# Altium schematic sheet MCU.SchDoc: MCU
size A3; DocumentNumber: MB1167; Revision: B.1; SheetNumber: 2; SheetTotal: 17; Project: STM327x6G-EVAL
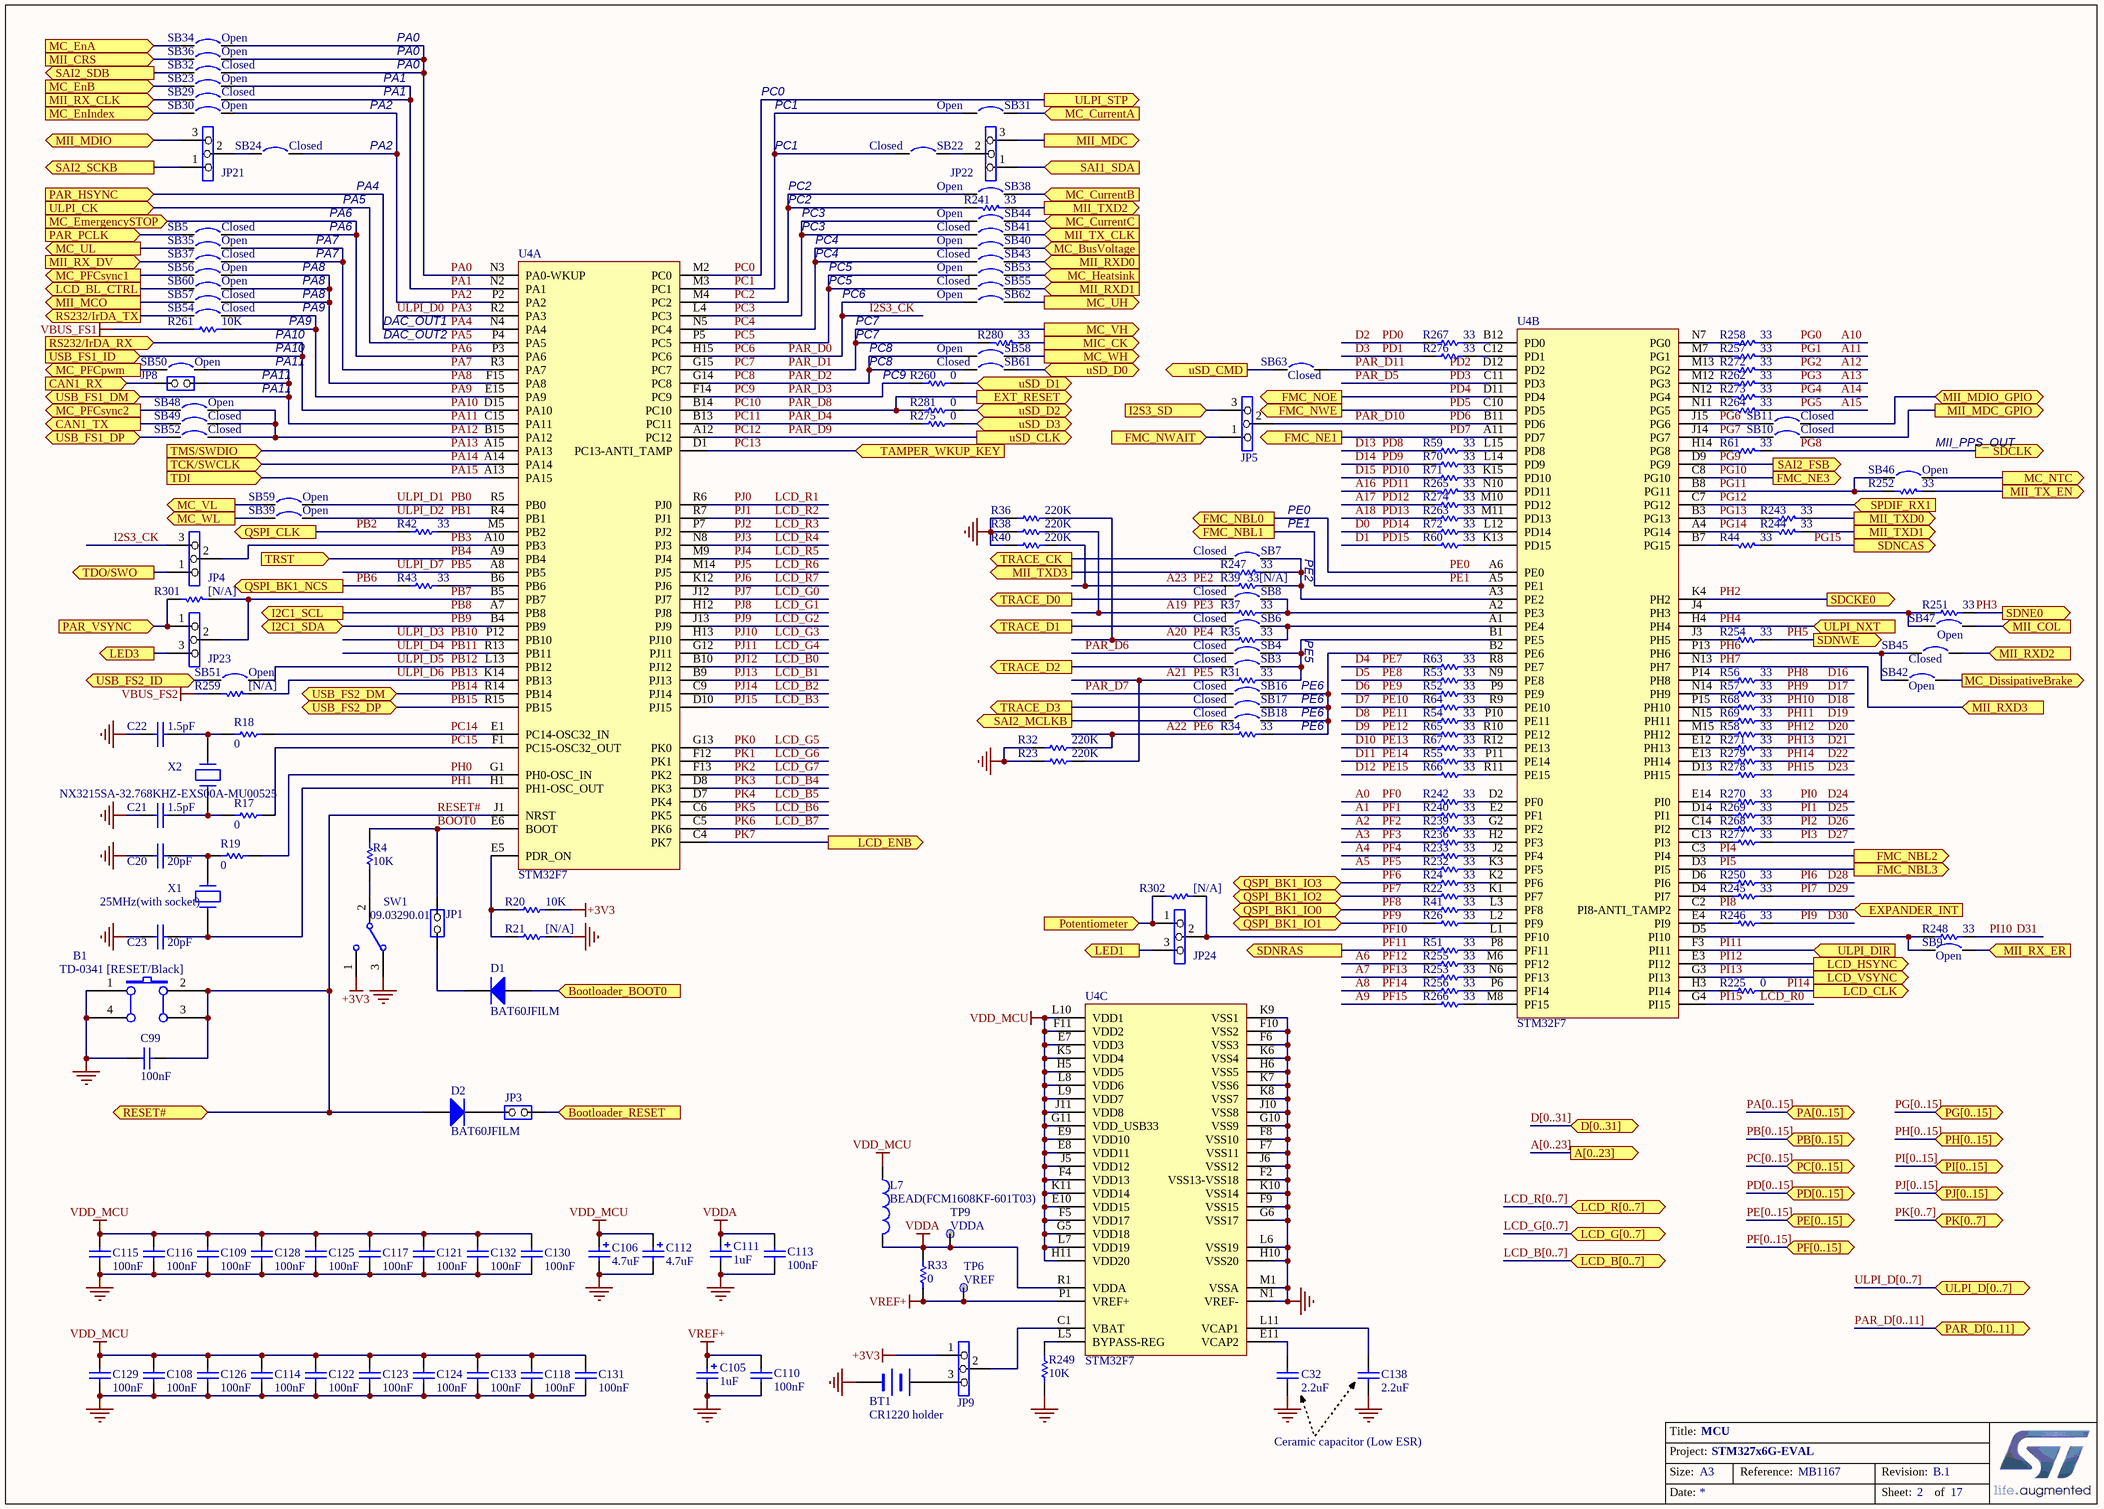
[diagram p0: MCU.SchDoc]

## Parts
B1  TD-0341 [RESET/Black]  [PB10]
BT1  CR1220 holder  [BAT_2SM_CR1220]
C20  20pF  [0603C]
C21  1.5pF  [0603C]
C22  1.5pF  [0603C]
C23  20pF  [0603C]
C32  2.2uF  [1206C]
C99  100nF  [0603C]
C105  1uF  [TAN-A]
C106  4.7uF  [TAN-A]
C108  100nF  [0402C]
C109  100nF  [0402C]
C110  100nF  [0402C]
C111  1uF  [TAN-A]
C112  4.7uF  [TAN-A]
C113  100nF  [0402C]
C114  100nF  [0402C]
C115  100nF  [0402C]
C116  100nF  [0402C]
C117  100nF  [0402C]
C118  100nF  [0402C]
C121  100nF  [0402C]
C122  100nF  [0402C]
C123  100nF  [0402C]
C124  100nF  [0402C]
C125  100nF  [0402C]
C126  100nF  [0402C]
C128  100nF  [0402C]
C129  100nF  [0402C]
C130  100nF  [0402C]
C131  100nF  [0402C]
C132  100nF  [0402C]
C133  100nF  [0402C]
C138  2.2uF  [1206C]
D1  BAT60JFILM  [SOD-323]
D2  BAT60JFILM  [SOD-323]
JP1  (no value)  [SIP2]
JP3  (no value)  [SIP2]
JP4  (no value)  [SIP3]
JP5  (no value)  [SIP3]
JP8  (no value)  [SIP2]
JP9  (no value)  [SIP3]
JP21  (no value)  [SIP3]
JP22  (no value)  [SIP3]
JP23  (no value)  [SIP3]
JP24  (no value)  [SIP3]
L7  BEAD(FCM1608KF-601T03)  [0603L]
R4  10K  [0603R]
R17  0  [0603R]
R18  0  [0603R]
R19  0  [0603R]
R20  10K  [0603R]
R21  [N/A]  [0603R]
R22  33  [0402R]
R23  220K  [0603R]
R24  33  [0402R]
R26  33  [0402R]
R31  33  [0402R]
R32  220K  [0603R]
R33  0  [0603R]
R34  33  [0402R]
R35  33  [0402R]
R36  220K  [0603R]
R37  33  [0402R]
R38  220K  [0603R]
R39  33[N/A]  [0402R]
R40  220K  [0603R]
R41  33  [0402R]
R42  33  [0402R]
R43  33  [0402R]
R44  33  [0402R]
R51  33  [0402R]
R52  33  [0402R]
R53  33  [0402R]
R54  33  [0402R]
R55  33  [0402R]
R56  33  [0402R]
R57  33  [0402R]
R58  33  [0402R]
R59  33  [0402R]
R60  33  [0402R]
R61  33  [0402R]
R63  33  [0402R]
R64  33  [0402R]
R65  33  [0402R]
R66  33  [0402R]
R67  33  [0402R]
R68  33  [0402R]
R69  33  [0402R]
R70  33  [0402R]
R71  33  [0402R]
R72  33  [0402R]
R225  0  [0603R]
R232  33  [0402R]
R233  33  [0402R]
R236  33  [0402R]
R239  33  [0402R]
R240  33  [0402R]
R241  33  [0603R]
R242  33  [0402R]
R243  33  [0603R]
R244  33  [0603R]
R245  33  [0402R]
R246  33  [0402R]
R247  33  [0603R]
R248  33  [0402R]
R249  10K  [0603R]
R250  33  [0402R]
R251  33  [0402R]
R252  33  [0603R]
R253  33  [0402R]
R254  33  [0402R]
R255  33  [0402R]
R256  33  [0402R]
R257  33  [0402R]
R258  33  [0402R]
R259  [N/A]  [0603R]
R260  0  [0603R]
R261  10K  [0603R]
R262  33  [0402R]
R263  33  [0402R]
R264  33  [0402R]
R265  33  [0402R]
R266  33  [0402R]
R267  33  [0402R]
R268  33  [0402R]
R269  33  [0402R]
R270  33  [0402R]
R271  33  [0402R]
R272  33  [0402R]
R273  33  [0402R]
R274  33  [0402R]
R275  0  [0603R]
R276  33  [0402R]
R277  33  [0402R]
R278  33  [0402R]
R279  33  [0402R]
R280  33  [0603R]
R281  0  [0603R]
R301  [N/A]  [0603R]
R302  [N/A]  [0603R]
SB3  Closed  [SB_0603]
SB4  Closed  [SB_0603]
SB5  Closed  [SB_0603]
SB6  Closed  [SB_0603]
SB7  Closed  [SB_0603]
SB8  Closed  [SB_0603]
SB9  Open  [SB_0603]
SB10  Closed  [SB_0603]
SB11  Closed  [SB_0603]
SB16  Closed  [SB_0603]
SB17  Closed  [SB_0603]
SB18  Closed  [SB_0603]
SB22  Closed  [SB_0603]
SB23  Open  [SB_0603]
SB24  Closed  [SB_0603]
SB29  Closed  [SB_0603]
SB30  Open  [SB_0603]
SB31  Open  [SB_0603]
SB32  Closed  [SB_0603]
SB34  Open  [SB_0603]
SB35  Open  [SB_0603]
SB36  Open  [SB_0603]
SB37  Closed  [SB_0603]
SB38  Open  [SB_0603]
SB39  Open  [SB_0603]
SB40  Open  [SB_0603]
SB41  Closed  [SB_0603]
SB42  Open  [SB_0603]
SB43  Closed  [SB_0603]
SB44  Open  [SB_0603]
SB45  Closed  [SB_0603]
SB46  Open  [SB_0603]
SB47  Open  [SB_0603]
SB48  Open  [SB_0603]
SB49  Closed  [SB_0603]
SB50  Open  [SB_0603]
SB51  Open  [SB_0603]
SB52  Closed  [SB_0603]
SB53  Open  [SB_0603]
SB54  Closed  [SB_0603]
SB55  Closed  [SB_0603]
SB56  Open  [SB_0603]
SB57  Closed  [SB_0603]
SB58  Open  [SB_0603]
SB59  Open  [SB_0603]
SB60  Open  [SB_0603]
SB61  Closed  [SB_0603]
SB62  Open  [SB_0603]
SB63  Closed  [SB_0603]
SW1  09.03290.01  [SW1_3TH_2R54_10X2R5]
TP6  VREF  [TP]
TP9  VDDA  [TP]
U4  STM32F7  [BGA216_0R8_13X13_SKT]  (parts A,B,C of 3)
X1  25MHz(with socket)  [XTAL_socket]
X2  NX3215SA-32.768KHZ-EXS00A-MU00525  [XTAL_2SM_3R2X1R5]

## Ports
A[0..23] (out), Bootloader_BOOT0 (in), Bootloader_RESET (in), CAN1_RX (in), CAN1_TX (out), D[0..31] (bidir), EXPANDER_INT (in), EXT_RESET (out), FMC_NBL0 (out), FMC_NBL1 (out), FMC_NBL2 (out), FMC_NBL3 (out), FMC_NE1 (out), FMC_NE3 (out), FMC_NOE (out), FMC_NWAIT (in), FMC_NWE (out), I2C1_SCL (out), I2C1_SDA (bidir), I2S3_SD (in), LCD_B[0..7] (bidir), LCD_BL_CTRL (out), LCD_CLK (out), LCD_ENB (out), LCD_G[0..7] (bidir), LCD_HSYNC (out), LCD_R[0..7] (bidir), LCD_VSYNC (out), LED1 (out), LED3 (out), MC_BusVoltage (in), MC_CurrentA (in), MC_CurrentB (in), MC_CurrentC (in), MC_DissipativeBrake (out), MC_EmergencySTOP (in), MC_EnA (in), MC_EnB (in), MC_EnIndex (in), MC_Heatsink (in), MC_NTC (out), MC_PFCpwm (out), MC_PFCsync1 (out), MC_PFCsync2 (out), MC_UH (out), MC_UL (out), MC_VH (out), MC_VL (out), MC_WH (out), MC_WL (out), MIC_CK (out), MII_COL (in), MII_CRS (in), MII_MCO (out), MII_MDC (out), MII_MDC_GPIO (out), MII_MDIO (bidir), MII_MDIO_GPIO (bidir), MII_RX_CLK (in), MII_RX_DV (in), MII_RX_ER (in), MII_RXD0 (in), MII_RXD1 (in), MII_RXD2 (in), MII_RXD3 (in), MII_TX_CLK (in), MII_TX_EN (out), MII_TXD0 (out), MII_TXD1 (out), MII_TXD2 (out), MII_TXD3 (out), PA[0..15] (bidir), PAR_D[0..11] (bidir), PAR_HSYNC (in), PAR_PCLK (in), PAR_VSYNC (in), PB[0..15] (bidir), PC[0..15] (bidir), PD[0..15] (bidir), PE[0..15] (bidir), PF[0..15] (bidir), PG[0..15] (bidir), PH[0..15] (bidir), PI[0..15] (bidir), PJ[0..15] (bidir), PK[0..7] (bidir), Potentiometer (in), QSPI_BK1_IO0 (bidir), QSPI_BK1_IO1 (bidir), QSPI_BK1_IO2 (bidir), QSPI_BK1_IO3 (bidir), QSPI_BK1_NCS (out), QSPI_CLK (out), RESET# (bidir), RS232/IrDA_RX (in), RS232/IrDA_TX (out), SAI1_SDA (in), SAI2_FSB (out), SAI2_MCLKB (out), SAI2_SCKB (out), SAI2_SDB (out), SDCKE0 (out), SDCLK (out), SDNCAS (out), SDNE0 (out), SDNRAS (out), SDNWE (out), SPDIF_RX1 (in), TAMPER_WKUP_KEY (in), TCK/SWCLK (in), TDI (in), TDO/SWO (out), TMS/SWDIO (in), TRACE_CK (out), TRACE_D0 (out), TRACE_D1 (out), TRACE_D2 (out), TRACE_D3 (out), TRST (in), ULPI_CK (in), ULPI_D[0..7] (bidir), ULPI_DIR (in), ULPI_NXT (in), ULPI_STP (out), USB_FS1_DM (bidir), USB_FS1_DP (bidir), USB_FS1_ID (in), USB_FS2_DM (bidir), USB_FS2_DP (bidir), USB_FS2_ID (bidir), uSD_CLK (out), uSD_CMD (out), uSD_D0 (bidir), uSD_D1 (bidir), uSD_D2 (bidir), uSD_D3 (bidir)

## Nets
+3V3: JP9.1 R20.2 SW1.1
GND: B1.1(A0) B1.4(A1) BT1.2(-) C20.2 C21.2 C22.2 C23.2 C32.2 C99.1 C105.2 C106.2 C108.2 C109.2 C110.1 C111.2 C112.2 C113.1 C114.2 C115.2 C116.2 C117.2 C118.2 C121.2 C122.2 C123.2 C124.2 C125.2 C126.2 C128.2 C129.2 C130.2 C131.2 C132.2 C133.2 C138.2 R21.2 R23.1 R32.1 R36.1 R38.1 R40.1 R249.1 SW1.3 U4.F2(VSS13-VSS18) U4.F6(VSS3) U4.F7(VSS11) U4.F8(VSS10) U4.F9(VSS15) U4.F10(VSS2) U4.G6(VSS17) U4.G10(VSS9) U4.H6(VSS5) U4.H10(VSS20) U4.J6(VSS12) U4.J10(VSS8) U4.K6(VSS4) U4.K7(VSS6) U4.K8(VSS7) U4.K9(VSS1) U4.K10(VSS14) U4.L6(VSS19) U4.M1(VSSA) U4.N1(VREF-)
VBUS_FS1: R261.2
VBUS_FS2: R259.1
VDD_MCU: C106.1 C108.1 C109.1 C112.1 C114.1 C115.1 C116.1 C117.1 C118.1 C121.1 C122.1 C123.1 C124.1 C125.1 C126.1 C128.1 C129.1 C130.1 C131.1 C132.1 C133.1 L7.1 U4.E7(VDD3) U4.E8(VDD11) U4.E9(VDD10) U4.E10(VDD15) U4.F4(VDD13) U4.F5(VDD17) U4.F11(VDD2) U4.G5(VDD18) U4.G11(VDD_USB33) U4.H5(VDD5) U4.H11(VDD20) U4.J5(VDD12) U4.J11(VDD8) U4.K5(VDD4) U4.K11(VDD14) U4.L7(VDD19) U4.L8(VDD6) U4.L9(VDD7) U4.L10(VDD1)
VDDA: C111.1 C113.2 L7.2 R33.1 TP9.1 U4.R1(VDDA)
VREF+: C105.1 C110.2 R33.2 TP6.1 U4.P1(VREF+)
A0: R242.2  [also labelled PF0]
A1: R240.2  [also labelled PF1]
A2: R239.2  [also labelled PF2]
A3: R236.2  [also labelled PF3]
A4: R233.2  [also labelled PF4]
A5: R232.2  [also labelled PF5]
A6: R255.2  [also labelled PF12]
A7: R253.2  [also labelled PF13]
A8: R256.2  [also labelled PF14]
A9: R266.2  [also labelled PF15]
A10: R258.2  [also labelled PG0]
A11: R257.2  [also labelled PG1]
A12: R272.2  [also labelled PG2]
A13: R262.2  [also labelled PG3]
A14: R273.2  [also labelled PG4]
A15: R264.2  [also labelled PG5]
A16: R265.1  [also labelled PD11]
A17: R274.2  [also labelled PD12]
A18: R263.2  [also labelled PD13]
A19: R37.2 R38.2  [also labelled PE3]
A20: R35.2 R36.2  [also labelled PE4]
A21: R23.2 R31.2  [also labelled PE5]
A22: R32.2 R34.2  [also labelled PE6]
A23: R39.2 R40.2  [also labelled PE2]
BOOT0: JP1.2(NO) R4.1 U4.E6(BOOT)
Bootloader_BOOT0: D1.1(A) ; port Bootloader_BOOT0
Bootloader_RESET: JP3.2(NO) ; port Bootloader_RESET
CAN1_RX: JP8.2(NO) ; port CAN1_RX
CAN1_TX: SB49.1 ; port CAN1_TX
D0: R72.2  [also labelled PD14]
D1: R60.2  [also labelled PD15]
D2: R267.2  [also labelled PD0]
D3: R276.2  [also labelled PD1]
D4: R63.2  [also labelled PE7]
D5: R53.2  [also labelled PE8]
D6: R52.2  [also labelled PE9]
D7: R64.2  [also labelled PE10]
D8: R54.2  [also labelled PE11]
D9: R65.2  [also labelled PE12]
D10: R67.2  [also labelled PE13]
D11: R55.2  [also labelled PE14]
D12: R66.2  [also labelled PE15]
D13: R59.2  [also labelled PD8]
D14: R70.2  [also labelled PD9]
D15: R71.2  [also labelled PD10]
D16: R56.1  [also labelled PH8]
D17: R57.1  [also labelled PH9]
D18: R68.1  [also labelled PH10]
D19: R69.1  [also labelled PH11]
D20: R58.1  [also labelled PH12]
D21: R271.1  [also labelled PH13]
D22: R279.1  [also labelled PH14]
D23: R278.1  [also labelled PH15]
D24: R270.1  [also labelled PI0]
D25: R269.1  [also labelled PI1]
D26: R268.1  [also labelled PI2]
D27: R277.1  [also labelled PI3]
D28: R250.1  [also labelled PI6]
D29: R245.1  [also labelled PI7]
D30: R246.1  [also labelled PI9]
D31: R248.1  [also labelled PI10]
FMC_NWAIT: JP5.1 ; port FMC_NWAIT
I2S3_CK: JP4.3 SB62.1 U4.H15(PC6)  [also labelled PAR_D0, PC6]
I2S3_SD: JP5.3 ; port I2S3_SD
LCD_B0: U4.B10(PJ12)  [also labelled PJ12]
LCD_B1: U4.B9(PJ13)  [also labelled PJ13]
LCD_B2: U4.C9(PJ14)  [also labelled PJ14]
LCD_B3: U4.D10(PJ15)  [also labelled PJ15]
LCD_B4: U4.D8(PK3)  [also labelled PK3]
LCD_B5: U4.D7(PK4)  [also labelled PK4]
LCD_B6: U4.C6(PK5)  [also labelled PK5]
LCD_B7: U4.C5(PK6)  [also labelled PK6]
LCD_BL_CTRL: SB60.1 ; port LCD_BL_CTRL
LCD_G0: U4.J12(PJ7)  [also labelled PJ7]
LCD_G1: U4.H12(PJ8)  [also labelled PJ8]
LCD_G2: U4.J13(PJ9)  [also labelled PJ9]
LCD_G3: U4.H13(PJ10)  [also labelled PJ10]
LCD_G4: U4.G12(PJ11)  [also labelled PJ11]
LCD_G5: U4.G13(PK0)  [also labelled PK0]
LCD_G6: U4.F12(PK1)  [also labelled PK1]
LCD_G7: U4.F13(PK2)  [also labelled PK2]
LCD_R0: U4.G4(PI15)  [also labelled PI15]
LCD_R1: U4.R6(PJ0)  [also labelled PJ0]
LCD_R2: U4.R7(PJ1)  [also labelled PJ1]
LCD_R3: U4.P7(PJ2)  [also labelled PJ2]
LCD_R4: U4.N8(PJ3)  [also labelled PJ3]
LCD_R5: U4.M9(PJ4)  [also labelled PJ4]
LCD_R6: U4.M14(PJ5)  [also labelled PJ5]
LCD_R7: U4.K12(PJ6)  [also labelled PJ6]
LED1: JP24.3 ; port LED1
LED3: JP23.3 ; port LED3
MC_BusVoltage: SB40.2 ; port MC_BusVoltage
MC_CurrentA: SB31.2 ; port MC_CurrentA
MC_CurrentB: SB38.2 ; port MC_CurrentB
MC_CurrentC: SB44.2 ; port MC_CurrentC
MC_DissipativeBrake: SB42.2 ; port MC_DissipativeBrake
MC_EnA: SB34.1 ; port MC_EnA
MC_EnB: SB23.1 ; port MC_EnB
MC_EnIndex: SB30.1 ; port MC_EnIndex
MC_Heatsink: SB53.2 ; port MC_Heatsink
MC_NTC: SB46.2 ; port MC_NTC
MC_PFCpwm: SB50.1 ; port MC_PFCpwm
MC_PFCsync1: SB56.1 ; port MC_PFCsync1
MC_PFCsync2: SB48.1 ; port MC_PFCsync2
MC_UH: SB62.2 ; port MC_UH
MC_UL: SB35.1 ; port MC_UL
MC_VL: SB59.1 ; port MC_VL
MC_WH: SB58.2 ; port MC_WH
MC_WL: SB39.1 ; port MC_WL
MIC_CK: R280.2 ; port MIC_CK
MII_COL: SB47.2 ; port MII_COL
MII_CRS: SB36.1 ; port MII_CRS
MII_MCO: SB57.1 ; port MII_MCO
MII_MDC: JP22.3 ; port MII_MDC
MII_MDC_GPIO: SB10.2 ; port MII_MDC_GPIO
MII_MDIO: JP21.3 ; port MII_MDIO
MII_MDIO_GPIO: SB11.2 ; port MII_MDIO_GPIO
MII_RX_CLK: SB29.1 ; port MII_RX_CLK
MII_RX_DV: SB37.1 ; port MII_RX_DV
MII_RX_ER: SB9.2 ; port MII_RX_ER
MII_RXD0: SB43.2 ; port MII_RXD0
MII_RXD1: SB55.2 ; port MII_RXD1
MII_RXD2: SB45.2 ; port MII_RXD2
MII_TX_CLK: SB41.2 ; port MII_TX_CLK
MII_TX_EN: R252.2 ; port MII_TX_EN
MII_TXD0: R243.2 ; port MII_TXD0
MII_TXD1: R244.2 ; port MII_TXD1
MII_TXD2: R241.2 ; port MII_TXD2
MII_TXD3: R247.1 ; port MII_TXD3
PA0: SB32.2 SB34.2 SB36.2 U4.N3(PA0-WKUP)
PA1: SB23.2 SB29.2 U4.N2(PA1)
PA2: SB24.2 SB30.2 U4.P2(PA2)
PA3: U4.R2(PA3)  [also labelled ULPI_D0]
PA4: U4.N4(PA4) ; port PAR_HSYNC
PA5: U4.P4(PA5) ; port ULPI_CK
PA6: SB5.2 U4.P3(PA6) ; port MC_EmergencySTOP
PA7: SB35.2 SB37.2 U4.R3(PA7)
PA8: SB56.2 SB57.2 SB60.2 U4.F15(PA8)
PA9: R261.1 SB54.2 U4.E15(PA9)
PA10: U4.D15(PA10) ; port RS232/IrDA_RX, port USB_FS1_ID
PA11: JP8.1(COMMON) SB50.2 U4.C15(PA11) ; port USB_FS1_DM
PA12: SB48.2 SB49.2 SB52.2 U4.B15(PA12)
PA13: U4.A15(PA13) ; port TMS/SWDIO
PA14: U4.A14(PA14) ; port TCK/SWCLK
PA15: U4.A13(PA15) ; port TDI
PAR_D1: R280.1 U4.G15(PC7) ; port MC_VH  [also labelled PC7]
PAR_D2: SB58.1 SB61.1 U4.G14(PC8)  [also labelled PC8]
PAR_D3: R260.2 U4.F14(PC9)  [also labelled PC9]
PAR_D4: R275.2 U4.B13(PC11)  [also labelled PC11]
PAR_D5: U4.C11(PD3)  [also labelled PD3]
PAR_D6: SB4.1
PAR_D7: SB16.1
PAR_D8: R281.2 U4.B14(PC10) ; port EXT_RESET  [also labelled PC10]
PAR_D9: U4.A12(PC12) ; port uSD_CLK  [also labelled PC12]
PAR_D10: JP5.2 U4.B11(PD6)  [also labelled PD6]
PAR_D11: SB63.2 U4.D12(PD2)  [also labelled PD2]
PAR_PCLK: SB5.1 ; port PAR_PCLK
PAR_VSYNC: JP23.1 R301.1 ; port PAR_VSYNC
PB0: SB59.2 U4.R5(PB0)  [also labelled ULPI_D1]
PB1: SB39.2 U4.R4(PB1)  [also labelled ULPI_D2]
PB2: R42.2 ; port QSPI_CLK
PB3: JP4.2 U4.A10(PB3)
PB4: U4.A9(PB4) ; port TRST
PB5: U4.A8(PB5)  [also labelled ULPI_D7]
PB6: R43.2 ; port QSPI_BK1_NCS
PB7: JP23.2 R301.2 U4.B5(PB7)
PB8: U4.A7(PB8) ; port I2C1_SCL
PB9: U4.B4(PB9) ; port I2C1_SDA
PB10: U4.P12(PB10)  [also labelled ULPI_D3]
PB11: U4.R13(PB11)  [also labelled ULPI_D4]
PB12: SB51.2 U4.L13(PB12)  [also labelled ULPI_D5]
PB13: R259.2 U4.K14(PB13)  [also labelled ULPI_D6]
PB14: U4.R14(PB14) ; port USB_FS2_DM
PB15: U4.R15(PB15) ; port USB_FS2_DP
PC0: U4.M2(PC0) ; port ULPI_STP
PC1: SB22.1 SB31.1 U4.M3(PC1)
PC2: R241.1 SB38.1 U4.M4(PC2)
PC3: SB41.1 SB44.1 U4.L4(PC3)
PC4: SB40.1 SB43.1 U4.N5(PC4)
PC5: SB53.1 SB55.1 U4.P5(PC5)
PC13: U4.D1(PC13-ANTI_TAMP) ; port TAMPER_WKUP_KEY
PC14: R18.2 U4.E1(PC14-OSC32_IN)
PC15: R17.2 U4.F1(PC15-OSC32_OUT)
PD4: U4.D11(PD4) ; port FMC_NOE
PD5: U4.C10(PD5) ; port FMC_NWE
PD7: U4.A11(PD7) ; port FMC_NE1
PE0: U4.A6(PE0) ; port FMC_NBL0
PE1: U4.A5(PE1) ; port FMC_NBL1
PF6: R24.2 ; port QSPI_BK1_IO3
PF7: R22.2 ; port QSPI_BK1_IO2
PF8: R41.2 ; port QSPI_BK1_IO0
PF9: R26.2 ; port QSPI_BK1_IO1
PF10: JP24.2 R302.2 U4.L1(PF10)
PF11: R51.2 ; port SDNRAS
PG6: SB11.1 U4.J15(PG6)
PG7: SB10.1 U4.J14(PG7)
PG8: R61.2 ; port SDCLK
PG9: U4.D9(PG9) ; port SAI2_FSB
PG10: U4.C8(PG10) ; port FMC_NE3
PG11: R252.1 SB46.1 U4.B8(PG11)
PG12: U4.C7(PG12) ; port SPDIF_RX1
PG13: R243.1 U4.B3(PG13)
PG14: R244.1 U4.A4(PG14)
PG15: R44.2 ; port SDNCAS
PH0: R19.1 U4.G1(PH0-OSC_IN)
PH1: C23.1 U4.H1(PH1-OSC_OUT) X1.1
PH2: U4.K4(PH2) ; port SDCKE0
PH3: R251.1 ; port SDNE0
PH4: U4.H4(PH4) ; port ULPI_NXT
PH5: R254.1 ; port SDNWE
PH6: SB42.1 SB45.1 U4.P13(PH6)
PH7: U4.N13(PH7) ; port MII_RXD3
PI4: U4.C3(PI4) ; port FMC_NBL2
PI5: U4.D3(PI5) ; port FMC_NBL3
PI8: U4.C2(PI8-ANTI_TAMP2) ; port EXPANDER_INT
PI11: U4.F3(PI11) ; port ULPI_DIR
PI12: U4.E3(PI12) ; port LCD_HSYNC
PI13: U4.G3(PI13) ; port LCD_VSYNC
PI14: R225.1 ; port LCD_CLK
PK7: U4.C4(PK7) ; port LCD_ENB
Potentiometer: JP24.1 R302.1 ; port Potentiometer
RESET#: B1.2(B0) B1.3(B1) C99.2 D2.1(A) U4.J1(NRST) ; port RESET#
RS232/IrDA_TX: SB54.1 ; port RS232/IrDA_TX
SAI1_SDA: JP22.1 ; port SAI1_SDA
SAI2_MCLKB: SB18.1 ; port SAI2_MCLKB
SAI2_SCKB: JP21.1 ; port SAI2_SCKB
SAI2_SDB: SB32.1 ; port SAI2_SDB
TDO/SWO: JP4.1 ; port TDO/SWO
TRACE_CK: SB7.1 ; port TRACE_CK
TRACE_D0: SB8.1 ; port TRACE_D0
TRACE_D1: SB6.1 ; port TRACE_D1
TRACE_D2: SB3.1 ; port TRACE_D2
TRACE_D3: SB17.1 ; port TRACE_D3
USB_FS1_DP: SB52.1 ; port USB_FS1_DP
USB_FS2_ID: SB51.1 ; port USB_FS2_ID
uSD_CMD: SB63.1 ; port uSD_CMD
uSD_D0: SB61.2 ; port uSD_D0
uSD_D1: R260.1 ; port uSD_D1
uSD_D2: R281.1 ; port uSD_D2
uSD_D3: R275.1 ; port uSD_D3
NetBT1_1: BT1.1(+) JP9.3
NetC20_1: C20.1 R19.2 X1.2
NetC21_1: C21.1 R17.1 X2.1
NetC22_1: C22.1 R18.1 X2.2
NetC32_1: C32.1 U4.E11(VCAP2)
NetC138_1: C138.1 U4.L11(VCAP1)
NetD1_2: D1.2(K) JP1.1(COMMON)
NetD2_2: D2.2(K) JP3.1(COMMON)
NetJP9_2: JP9.2 U4.C1(VBAT)
NetJP21_2: JP21.2 SB24.1
NetJP22_2: JP22.2 SB22.2
NetR4_2: R4.2 SW1.2
NetR20_1: R20.1 R21.1 U4.E5(PDR_ON)
NetR22_1: R22.1 U4.K1(PF7)
NetR24_1: R24.1 U4.K2(PF6)
NetR26_1: R26.1 U4.L2(PF9)
NetR31_1: R31.1 SB3.2 SB4.2 U4.B1(PE5)
NetR34_1: R34.1 SB16.2 SB17.2 SB18.2 U4.B2(PE6)
NetR35_1: R35.1 SB6.2 U4.A1(PE4)
NetR37_1: R37.1 SB8.2 U4.A2(PE3)
NetR39_1: R39.1 R247.2 SB7.2 U4.A3(PE2)
NetR41_1: R41.1 U4.L3(PF8)
NetR42_1: R42.1 U4.M5(PB2)
NetR43_1: R43.1 U4.B6(PB6)
NetR44_1: R44.1 U4.B7(PG15)
NetR51_1: R51.1 U4.P8(PF11)
NetR52_1: R52.1 U4.P9(PE9)
NetR53_1: R53.1 U4.N9(PE8)
NetR54_1: R54.1 U4.P10(PE11)
NetR55_1: R55.1 U4.P11(PE14)
NetR56_2: R56.2 U4.P14(PH8)
NetR57_2: R57.2 U4.N14(PH9)
NetR58_2: R58.2 U4.M15(PH12)
NetR59_1: R59.1 U4.L15(PD8)
NetR60_1: R60.1 U4.K13(PD15)
NetR61_1: R61.1 U4.H14(PG8)
NetR63_1: R63.1 U4.R8(PE7)
NetR64_1: R64.1 U4.R9(PE10)
NetR65_1: R65.1 U4.R10(PE12)
NetR66_1: R66.1 U4.R11(PE15)
NetR67_1: R67.1 U4.R12(PE13)
NetR68_2: R68.2 U4.P15(PH10)
NetR69_2: R69.2 U4.N15(PH11)
NetR70_1: R70.1 U4.L14(PD9)
NetR71_1: R71.1 U4.K15(PD10)
NetR72_1: R72.1 U4.L12(PD14)
NetR225_2: R225.2 U4.H3(PI14)
NetR232_1: R232.1 U4.K3(PF5)
NetR233_1: R233.1 U4.J2(PF4)
NetR236_1: R236.1 U4.H2(PF3)
NetR239_1: R239.1 U4.G2(PF2)
NetR240_1: R240.1 U4.E2(PF1)
NetR242_1: R242.1 U4.D2(PF0)
NetR245_2: R245.2 U4.D4(PI7)
NetR246_2: R246.2 U4.E4(PI9)
NetR248_2: R248.2 SB9.1 U4.D5(PI10)
NetR249_2: R249.2 U4.L5(BYPASS-REG)
NetR250_2: R250.2 U4.D6(PI6)
NetR251_2: R251.2 SB47.1 U4.J4(PH3)
NetR253_1: R253.1 U4.N6(PF13)
NetR254_2: R254.2 U4.J3(PH5)
NetR255_1: R255.1 U4.M6(PF12)
NetR256_1: R256.1 U4.P6(PF14)
NetR257_1: R257.1 U4.M7(PG1)
NetR258_1: R258.1 U4.N7(PG0)
NetR262_1: R262.1 U4.M12(PG3)
NetR263_1: R263.1 U4.M11(PD13)
NetR264_1: R264.1 U4.N11(PG5)
NetR265_2: R265.2 U4.N10(PD11)
NetR266_1: R266.1 U4.M8(PF15)
NetR267_1: R267.1 U4.B12(PD0)
NetR268_2: R268.2 U4.C14(PI2)
NetR269_2: R269.2 U4.D14(PI1)
NetR270_2: R270.2 U4.E14(PI0)
NetR271_2: R271.2 U4.E12(PH13)
NetR272_1: R272.1 U4.M13(PG2)
NetR273_1: R273.1 U4.N12(PG4)
NetR274_1: R274.1 U4.M10(PD12)
NetR276_1: R276.1 U4.C12(PD1)
NetR277_2: R277.2 U4.C13(PI3)
NetR278_2: R278.2 U4.D13(PH15)
NetR279_2: R279.2 U4.E13(PH14)

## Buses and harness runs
bus A[0..23] = port A[0..23]
bus D[0..31] = port D[0..31]
bus LCD_B[0..7] = port LCD_B[0..7]
bus LCD_G[0..7] = port LCD_G[0..7]
bus LCD_R[0..7] = port LCD_R[0..7]
bus PA[0..15] = port PA[0..15]
bus PAR_D[0..11] = port PAR_D[0..11]
bus PB[0..15] = port PB[0..15]
bus PC[0..15] = port PC[0..15]
bus PD[0..15] = port PD[0..15]
bus PE[0..15] = port PE[0..15]
bus PF[0..15] = port PF[0..15]
bus PG[0..15] = port PG[0..15]
bus PH[0..15] = port PH[0..15]
bus PI[0..15] = port PI[0..15]
bus PJ[0..15] = port PJ[0..15]
bus PK[0..7] = port PK[0..7]
bus ULPI_D[0..7] = port ULPI_D[0..7]

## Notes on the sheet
- PA0
- PA2
- PA1
- PC0
- PC1
- PA7
- PA6
- PA5
- PA4
- PC2
- PC3
- PC4
- PA8
- PA9
- PC5
- PC6
- PA11
- PA10
- DAC_OUT1
- DAC_OUT2
- PC7
- PC8
- PC9
- MII_PPS_OUT
- PE0
- PE1
- PE2
- PE5
- PE6
- Ceramic capacitor (Low ESR)

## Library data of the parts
B1 = SW PUSHBUTTON: SE PUSHBUTTON
BT1 = BATTERY
C20-C23 C108 C109 C114-C118 C121-C126 C128-C133 = CAP: Capacitor
C32 C110 C113 C138 = Cap: Capacitor; Value: 10nF
C99 = CAP: Capacitor; Value: 100pF
C105 C111 = Cap Pol1: Polarized Capacitor (Radial); Value: 10uF
C106 C112 = Cap Pol1: Polarized Capacitor (Radial); Value: 47uF
D1 D2 = Diode: Default Diode; Code - JEDEC: DO-214-AB
JP1 JP3 JP8 = JP2
JP4 JP5 JP9 JP21-JP24 = Jumper3
L7 = Inductor: Value: 100uH
R4 R23 R32 R36 R38 R40 R261 = res1: Resistor; Value: 1K
R17-R22 R24 R26 R31 R33-R35 R37 R39 R41-R44 R51-R61 R63-R72 R225 R232 R233 R236 R239-R260 R262-R281 R301 R302 = Res1: Resistor; Value: 1K
SB3-SB8 SB10 SB11 SB16-SB18 SB22 SB24 SB29 SB32 SB37 SB41 SB43 SB45 SB49 SB52 SB54 SB55 SB57 SB61 SB63 = Circuit Breaker_close: Circuit Breaker
SB9 SB23 SB30 SB31 SB34-SB36 SB38-SB40 SB42 SB44 SB46-SB48 SB50 SB51 SB53 SB56 SB58-SB60 SB62 = Circuit Breaker
SW1 = SW-SPDT: SPDT Subminiature Toggle Switch, Right Angle Mounting, Vertical Actuation; Revision 1: Jul-2002: Re-released for DXP Platform.; Revision 2: 17-Dec-2003: Schematic revised, PCB Footprint replaced.
TP6 TP9 = TP
U4 = STM32F7_TFBGA216
X1 = CRYSTAL
X2 = CRYSTAL_32K: Crystal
